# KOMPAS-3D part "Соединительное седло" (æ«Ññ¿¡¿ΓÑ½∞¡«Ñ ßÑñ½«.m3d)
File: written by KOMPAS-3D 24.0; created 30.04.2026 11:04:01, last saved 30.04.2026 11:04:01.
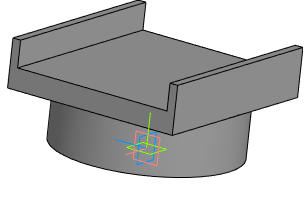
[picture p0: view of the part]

Document properties: Автор: USG_411; Полное имя файла: C:\Users\USG_411\Desktop\ИА-2904_411-12\Балка\Соединительное седло.m3d

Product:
- Part/product: Соединительное седло
    Масса: 55.246581

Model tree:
1. Эскиз:1
2. Элемент выдавливания:1
     Расстояние 1 = 100
3. Эскиз:2  (with: Грань.Элемент выдавливания:1)
4. Элемент выдавливания:2
     Расстояние 1 = 40
5. Эскиз:3  (with: Грань.Элемент выдавливания:2, Ребро.Элемент выдавливания:2)
6. Элемент выдавливания:3
     Расстояние 1 = 50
